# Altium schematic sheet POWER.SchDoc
size A4; SheetNumber: 2; SheetTotal: 3
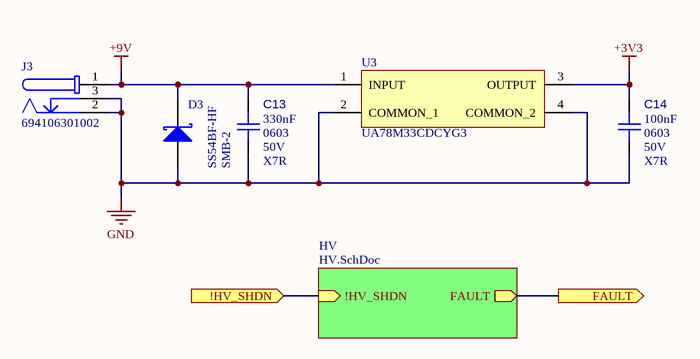
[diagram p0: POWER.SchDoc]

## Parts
?  (no value)
C13  value 330nF  Rated DC Voltage (URdc): 50V  Case/Package: 0603  Dielectric: X7R  [CAPC1608X10N]  (hidden comment: C1608X7R1H334K080AC)
C14  value 100nF  Voltage Rating: 50V  Case/Package: 0603  Dielectric: X7R  [CAPC1608X09N]  (hidden comment: CGA3E2X7R1H104K080AA)
D3  SS54BF-HF  Case/Package: SMB-2  [JCET-SMB-2_N]
J3  694106301002  [694106301002]
U3  UA78M33CDCYG3  [SOT-223-DB3_N]

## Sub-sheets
HV = HV.SchDoc: FAULT (out), !HV_SHDN (in)

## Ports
!HV_SHDN (in), FAULT (out)

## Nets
+3V3: C14.1 U3.3(OUTPUT)
+9V: C13.1 D3.2(K) J3.1 U3.1(INPUT)
GND: C13.2 C14.2 D3.1(A) J3.2 J3.3 U3.2(COMMON_1) U3.4(COMMON_2)
!HV_SHDN: port !HV_SHDN, sheet HV/!HV_SHDN
FAULT: port FAULT, sheet HV/FAULT

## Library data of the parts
? = CMP-00003-4: The KETS Schematic Sheet Title Block
C13 = CMP-001-00114-1: Ceramic Capacitor, Multilayer, Ceramic, 50V, 10% +Tol, 10% -Tol, X7R, 15% TC, 0.33uF, Surface Mount, 0603; Multilayer: Yes
C14 = CMP-001-00101-1: Ceramic Capacitor, Multilayer, Ceramic, 50V, 10% +Tol, 10% -Tol, X7R, 15% TC, 0.1uF, Surface Mount, 0603; Reference Standard: AEC-Q200; Multilayer: Yes
D3 = CMP-004-00006-3: Rectifier Diode, Schottky, 1 Phase, 1 Element, 5A, 40V V(RRM), Silicon; Manufacturer: JCET; Forward Voltage: 550mV; Peak Reverse Current: 1mA; Max Forward Surge Current (Ifsm): 120A; Number of Elements: 1
J3 = CMP-002-00210-1: DC Power Jack Connector WR-DC, Male, Right Angled, THT, 5 A, 24 V; Max Current Rating: 5A; Shielding: Unshielded; Operating Supply Voltage: 24V; Insulation Resistance: 100MΩ; Number of Contacts: 3
U3 = CMP-00395-1: Standard Regulator Pos 3.3V 0.5A 4-Pin(3+Tab) SOT-223 Tube; Manufacturer Lifecycle Status: ACTIVE; Quiescent Current: 4.5mA; Dropout Voltage: 2V; Power Supply Rejection Ratio (PSRR): 80dB; Polarity: Positive; Number of Outputs: 1; Max Output current: 500mA; Min Input Voltage: 5.3V; Max Supply Voltage: 25V; Output Type: Fixed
